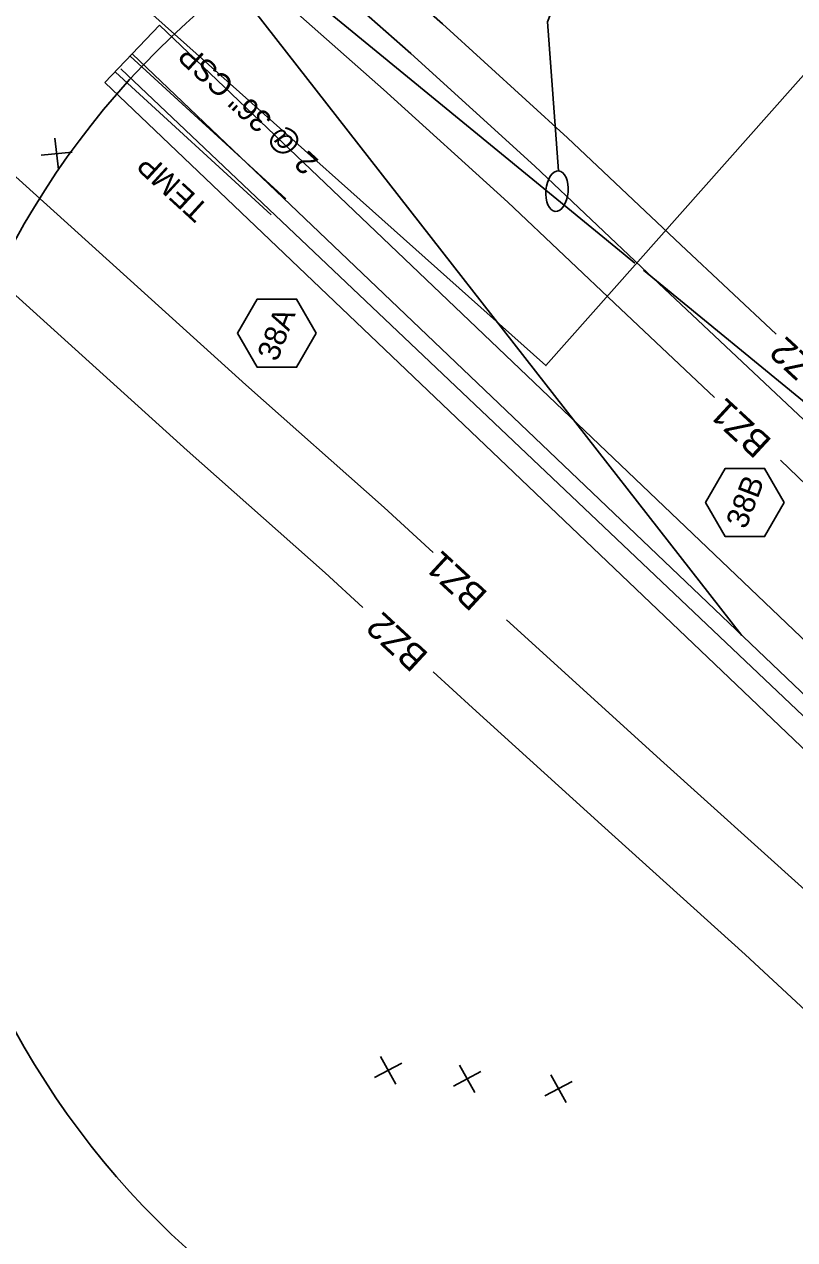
# Model space of a CAD drawing. Extents: x 2384780 to 2405432, y 547869 to 573706.
# Drawn here: x 2395831.8 to 2396006.8, y 557527 to 557803.2 of the extents above; entities that cross this region are included whole.
import ezdxf

# ---------------------------------------------------------------- set-up
doc = ezdxf.new("R2010")
doc.units = 0
for name, color, linetype in [('Old_Level_18', 7, 'Continuous'), ('Old_Level_5', 7, 'Continuous'), ('Old_Level_62', 7, 'Continuous'), ('Old_Level_63', 7, 'Continuous'), ('Prop Buffer Zone 1', 7, 'Continuous'), ('Prop Buffer Zone 2', 7, 'Continuous'), ('Prop Drainage Box Number Symbol CELL', 7, 'Continuous'), ('Prop Drainage Structure Pipe CSP 36in', 7, 'Continuous')]:
    doc.layers.add(name, color=color, linetype=linetype)

msp = doc.modelspace()

# ---------------------------------------------------------------- linework, layer by layer
at = {"layer": 'Old_Level_18'}
for p, q in [((2395967.77, 557751.14), (2395879.48, 557823.59)), ((2395967.77, 557751.14), (2395970.49, 557748.91)), ((2395972.45, 557747.3), (2396012.33, 557714.58))]:
    msp.add_line(p, q, dxfattribs=at)
msp.add_lwpolyline([(2395953.46, 557811.19), (2395950.61, 557803.78), (2395953.15, 557769.91)], dxfattribs=at)
msp.add_ellipse((2395952.77, 557765.3), major_axis=(0.38, 4.6), ratio=0.548538, dxfattribs=at)
at = {"layer": 'Old_Level_62'}
msp.add_lwpolyline([(2396034.81, 558046.95), (2396309.7, 558569.81), (2396830.12, 558678.33), (2396873.09, 558636.56), (2396463.4, 558263.16), (2396226.67, 558037.32), (2395950.25, 557725.64), (2395851.08, 557814.24)], close=True, dxfattribs=at)
at = {"layer": 'Old_Level_63'}
for p, q in [((2395862.49, 557803.03), (2395850.06, 557790.01)), ((2396125.98, 557551.5), (2395862.49, 557803.03)), ((2396112.6, 557551.84), (2395856.27, 557796.52)), ((2395853.67, 557793.1), (2396115.7, 557544.47)), ((2396101.99, 557549.52), (2395850.06, 557790.01)), ((2395839.51, 557770.25), (2395838.7, 557777.37)), ((2395842.61, 557774.16), (2395835.6, 557773.46)), ((2395917.53, 557567.12), (2395911.32, 557563.8)), ((2395916.16, 557562.32), (2395912.69, 557568.59)), ((2395934.1, 557560.39), (2395930.63, 557566.67)), ((2395935.47, 557565.19), (2395929.26, 557561.87)), ((2395954.84, 557558.16), (2395951.38, 557564.43)), ((2395956.21, 557562.96), (2395950, 557559.64))]:
    msp.add_line(p, q, dxfattribs=at)
for points in [[(2395994.8, 557664.28), (2395067.49, 558852.81), (2394796, 558825.57)], [(2396112.74, 557615.61), (2395973.35, 557746.71), (2395947.75, 557770.96), (2395919.54, 557796.6), (2395894.98, 557818.31)]]:
    msp.add_lwpolyline(points, dxfattribs=at)
msp.add_circle((2395994.8, 557664.28), 187.94, dxfattribs=at)
at = {"layer": 'Prop Buffer Zone 1'}
for points in [[(2395988.58, 557718.42), (2395967.2, 557738.53), (2395941.59, 557762.77), (2395913.38, 557788.42), (2395888.73, 557810.21), (2395856.06, 557837.97), (2395827.45, 557863.67), (2395800.63, 557888.15), (2395772.33, 557913.85), (2395748.82, 557934.16), (2395727.63, 557952.91), (2395703.38, 557975.74), (2395672.58, 558003.69), (2395650.27, 558024.36)], [(2395603.74, 557969.25), (2395638.42, 557940.99), (2395672.93, 557910.8), (2395703.2, 557882.86), (2395728.68, 557860.35), (2395766.51, 557826.35), (2395808.56, 557787.68), (2395840.81, 557758.61), (2395882.12, 557721.24), (2395913.53, 557693.36), (2395924.65, 557683.16)], [(2396151.8, 557564.96), (2396068.71, 557645.26), (2396055.1, 557657.56), (2396040.38, 557671.31), (2396011.4, 557696.61), (2396003.51, 557704.16)], [(2395941.31, 557667.88), (2395947.07, 557662.6), (2395976.29, 557636.07), (2396009.04, 557606.52), (2396047.88, 557570.44), (2396073.11, 557548.56), (2396077.08, 557544.64)]]:
    msp.add_lwpolyline(points, dxfattribs=at)
at = {"layer": 'Prop Buffer Zone 2'}
for points in [[(2396002.53, 557732.75), (2395980.92, 557753.08), (2395955.19, 557777.44), (2395926.73, 557803.31), (2395901.83, 557825.32), (2395869.22, 557853.03), (2395840.87, 557878.49), (2395814.09, 557902.94), (2395785.59, 557928.82), (2395761.98, 557949.22), (2395741.11, 557967.68), (2395716.95, 557990.43), (2395686.09, 558018.43), (2395663.86, 558039.04)], [(2395590.44, 557954.29), (2395625.51, 557925.71), (2395659.56, 557895.92), (2395689.79, 557868.01), (2395715.37, 557845.42), (2395753.05, 557811.55), (2395795.09, 557772.89), (2395827.4, 557743.76), (2395868.77, 557706.35), (2395900.13, 557678.51), (2395908.67, 557670.68)], [(2395924.61, 557656.06), (2395933.59, 557647.83), (2395962.87, 557621.25), (2395995.54, 557591.77), (2396034.52, 557555.55), (2396057.01, 557536.05)]]:
    msp.add_lwpolyline(points, dxfattribs=at)
at = {"layer": 'Prop Drainage Box Number Symbol CELL'}
for points in [[(2395898.09, 557733.02), (2395893.62, 557740.77), (2395884.67, 557740.77), (2395880.19, 557733.02), (2395884.67, 557725.27), (2395893.62, 557725.27)], [(2396004.41, 557694.52), (2395999.94, 557702.27), (2395990.99, 557702.27), (2395986.51, 557694.52), (2395990.99, 557686.77), (2395999.94, 557686.77)]]:
    msp.add_lwpolyline(points, close=True, dxfattribs=at)
at = {"layer": 'Prop Drainage Structure Pipe CSP 36in'}
for p, q in [((2395855.82, 557796.01), (2395891.21, 557763.58)), ((2395852.45, 557792.32), (2395887.84, 557759.89))]:
    msp.add_line(p, q, dxfattribs=at)

# ---------------------------------------------------------------- texts
at = {"layer": 'Old_Level_5'}
for s, p in [('2 @ 36" CSP', (2395898.85, 557772.27)), ('TEMP', (2395873.97, 557761.62))]:
    msp.add_text(s, height=5, rotation=137.5023, dxfattribs=at).set_placement(p)
at = {"layer": 'Prop Buffer Zone 1'}
for p in [(2396001.85, 557708.61), (2395937.3, 557673.9)]:
    msp.add_text('BZ1', height=6, rotation=137.2574, dxfattribs=at).set_placement(p)
at = {"layer": 'Prop Buffer Zone 2'}
for p in [(2396015.49, 557722.57), (2395923.85, 557660.03)]:
    msp.add_text('BZ2', height=6, rotation=137.2574, dxfattribs=at).set_placement(p)
at = {"layer": 'Prop Drainage Box Number Symbol CELL'}
for s, p in [('38A', (2395889.19, 557726.36)), ('38B', (2395995.67, 557688.28))]:
    msp.add_text(s, height=5, rotation=69.0001, dxfattribs=at).set_placement(p)

doc.saveas('drawing.dxf')
